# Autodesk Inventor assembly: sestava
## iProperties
Shininess: 64.0
Length Units: 11269
Angle Units: 11279
Time Units: 11290
Mass Units: 11283
Length Display Precision: 3
Angle Display Precision: 2
Compacted: True
Created: 2008-05
Part Number: sestava
Document SubType Name: Assembly
Designer: ikv
Manufacturer: Standard
Standards Organization: Custom
Density: 0.0
Volumn: 0.0
Area: 0.0
PropertySet Name: Model Information
Control State: 0
Master: False
Checked Out: False
Author: ikv
